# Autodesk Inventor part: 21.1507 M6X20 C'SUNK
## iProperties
Created: 2006-12
Part Number: 21.1507 M6X20 C'SUNK
Material: Steel, Mild
Description: Hexagon socket countersunk head cap screws
Document SubType Name: Modeling
Standard: DIN 7991
Designer: Andy Moles
Standards Organization: DIN
Language: en-US
Size Designation: M6x20
Categories: <MemberInstance Version="R10.0.0"><Categories><Category DisplayName="Fasteners" InternalName="e4da775c-781d-43d5-af7c-5136215cf5a6" Mnemonic="FSTN"><Category Di
Mass: 5.2442 g
Surface Area: 6.15988 cm^2
Volume: 0.667201 cm^3
Density: 7.86 g/cm^3
Author: Andy Moles
Revision Number: 1
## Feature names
1. Revolution1
2. Extrusion1
3. Fillet1
4. Chamfer1
